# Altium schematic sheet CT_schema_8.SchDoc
size 278 x 170 mm
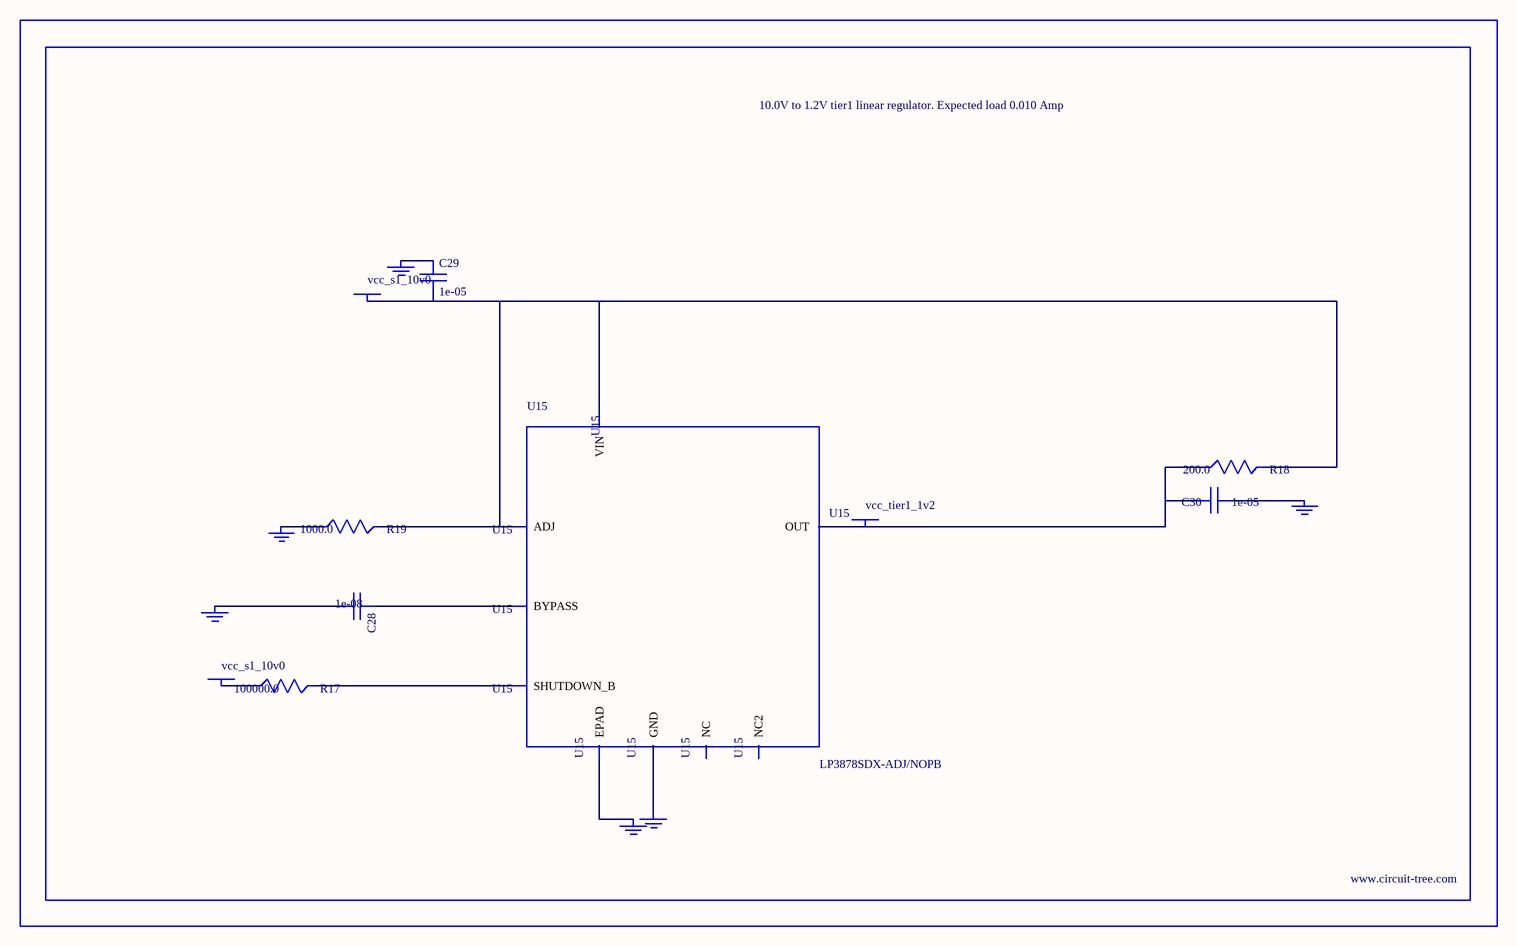
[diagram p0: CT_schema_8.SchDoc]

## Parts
BORDER7  (no value)
C28  1e-08  [C0402]
C29  1e-05  [C1206]
C30  1e-05  [C0805]
GND_INSTANCE_7_0  (no value)
GND_INSTANCE_7_1  (no value)
GND_INSTANCE_7_2  (no value)
GND_INSTANCE_7_3  (no value)
GND_INSTANCE_7_4  (no value)
GND_INSTANCE_7_5  (no value)
POWER_INSTANCE_7_0  vcc_s1_10v0
POWER_INSTANCE_7_1  vcc_s1_10v0
POWER_INSTANCE_7_2  vcc_tier1_1v2
R17  100000.0  [R0603]
R18  200.0  [R0603]
R19  1000.0  [R0603]
U15  LP3878SDX-ADJ/NOPB  [WSON-8]

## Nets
NetC28_1: C28.1 U15.1(BYPASS)
NetC28_2: C28.2 GND_INSTANCE_7_0.0(GND)
NetC29_1: C29.1 GND_INSTANCE_7_1.0(GND)
NetC29_2: C29.2 POWER_INSTANCE_7_0.0(PWR) R18.2 R19.2 U15.4(VIN) U15.6(ADJ)
NetC30_1: C30.1 GND_INSTANCE_7_2.0(GND)
NetC30_2: C30.2 POWER_INSTANCE_7_2.0(PWR) R18.1 U15.5(OUT)
NetGND_INSTANCE_7_3_0: GND_INSTANCE_7_3.0(GND) R19.1
NetGND_INSTANCE_7_4_0: GND_INSTANCE_7_4.0(GND) U15.PAD(EPAD)
NetGND_INSTANCE_7_5_0: GND_INSTANCE_7_5.0(GND) U15.3(GND)
NetPOWER_INSTANCE_7_1_0: POWER_INSTANCE_7_1.0(PWR) R17.1
NetR17_2: R17.2 U15.8(SHUTDOWN_B)

Not connected (* = marked no-connect by the designer): U15 2(NC) 7(NC2)

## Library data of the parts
BORDER7 = BORDER_PAGE7
C28 = C0402C103K3RAC
C29 = C1206C106K3RACTU
C30 = GRM219R60J106ME19D
GND_INSTANCE_7_0-GND_INSTANCE_7_5 = GND
POWER_INSTANCE_7_0-POWER_INSTANCE_7_2 = PWR
R17 = RC0603JR-07100KL
R18 = RC0603JR-07200RL
R19 = RC0603JR-071KL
